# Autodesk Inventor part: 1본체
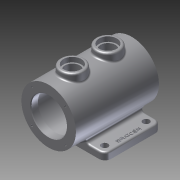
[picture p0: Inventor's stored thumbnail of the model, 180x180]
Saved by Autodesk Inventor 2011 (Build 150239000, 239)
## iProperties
Created: 2014-12
Part Number: 1본체
Document SubType Name: Modeling
Designer: user
Density: 1 g/cm^3
Mass: 477.257 g
Surface Area: 1040.04 cm^2
Volume: 477.257 cm^3
Author: user
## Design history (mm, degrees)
sketch "스케치1"
  geometry: L1 (0, 0)-(130, 0); L2 (130, 0)-(130, 95); L3 (130, 95)-(0, 95); L4 (0, 95)-(0, 0)
  constraints: 8 end point, 2 parallel, 1 horizontal, 1 perpendicular
  dimensions: "d0" = 130 distance of L3.end L2.end; "d1" = 95 distance of L2.end L1.end
extrude "돌출1" new body sketch "스케치1" distance "d2" = 12; taper "d3" = 0 deg
sketch "스케치2" dims "d23" = 37.5
  geometry: L1 (0, 0)-(0, 12) reference; L2 (0, 0)-(130, 0) reference; L3 (130, 12)-(130, 0) reference; L4 (130, 0)-(0, 0) reference; L5 (0, 0)-(0, 12) reference; L6 (0, 12)-(130, 12) reference; C1 r 46 at (65, 50)
  constraints: 1 centre point
  dimensions: "d4" = 92 diameter of C1; "d5" = 50 distance from line of L2 C1.centre; "d6" = 65 distance from line of L1 C1.centre
extrude "돌출2" join sketch "스케치2" distance "d7" = 30; taper "d9" = 0 deg; dims "d8" = 110, "d10" = 0
node "작업 평면1"
sketch "스케치3"
  geometry: L1 (-96, -30)-(-96, 110) reference; L2 (-96, 110)-(-4, 110) reference; L3 (-4, 110)-(-4, 95) reference; L4 (-4, 95)-(0, 95) reference; L5 (0, 95)-(0, 0) reference; L6 (0, 0)-(-4, 0) reference; L7 (-4, 0)-(-4, -30) reference; L8 (-4, -30)-(-96, -30) reference; L9 (-106, -10)-(-58.648, -10); L10 (-58.648, -10)-(-58.648, 10); L11 (-58.648, 10)-(-106, 10); L12 (-106, 10)-(-106, -10)
  constraints: 8 end point, 2 parallel, 1 horizontal, 1 perpendicular
  dimensions: "d11" = 40 distance between parallel lines of L8 L11; "d12" = 20 distance of L11.end L9.start; "d13" = 106 distance between parallel lines of L5 L12
revolve "회전1" sketch "스케치3" stored, may be unused: angle "d14" = 90 deg
sketch "스케치4"
  geometry: L1 (-4, 0)-(-4, -30) reference; L2 (-4, -30)-(-96, -30) reference; L3 (-96, -30)-(-96, -10) reference; L4 (-96, -10)-(-106, -10) reference; L5 (-106, -10)-(-106, 30) reference; L6 (-106, 30)-(-96, 30) reference; L7 (-96, 30)-(-96, 110) reference; L8 (-96, 110)-(-4, 110) reference; L9 (-4, 110)-(-4, 95) reference; L10 (-4, 95)-(0, 95) reference; L11 (0, 95)-(0, 0) reference; L12 (0, 0)-(-4, 0) reference; L13 (-106, 70)-(-64.183, 70); L14 (-64.183, 70)-(-64.183, 90); L15 (-64.183, 90)-(-106, 90); L16 (-106, 90)-(-106, 70)
  constraints: 8 end point, 2 parallel, 1 horizontal, 1 perpendicular
  dimensions: "d15" = 40 distance between parallel lines of L8 L13; "d16" = 20 distance of L15.end L13.start; "d17" = 106 distance between parallel lines of L11 L16
revolve "회전2" sketch "스케치4" stored, may be unused: angle "d18" = 90 deg
node "작업 평면2"
sketch "스케치5"
  geometry: L1 (-111, -30)-(-111, 110) reference; L2 (-111, 110)-(-19, 110) reference; L3 (-19, 110)-(-19, -30) reference; L4 (-19, -30)-(-111, -30) reference; L5 (-95, -42.03)-(-65, -42.03); L6 (-65, -42.03)-(-65, 144.703); L7 (-65, 144.703)-(-95, 144.703); L8 (-102.5, -18)-(-95, -18); L9 (-65, -18)-(-65, 98); L10 (-95, 98)-(-102.5, 98); L11 (-102.5, 98)-(-102.5, -18); L12 (-95, 144.703)-(-95, 98); L13 (-95, -18)-(-95, -42.03); 1 further point
  constraints: 18 end point, 5 parallel, 2 horizontal, 2 perpendicular, 1 point on line
  dimensions: "d20" = 46 distance between parallel lines of L1 L6; "d21" = 92 distance between parallel lines of L3 L1 (derived); "d23" = 37.5 distance between parallel lines of L6 L11; "d24" = 12 distance between parallel lines of L2 L10; "d25" = 12 distance between parallel lines of L4 L8
revolve "회전3" sketch "스케치5" stored, may be unused: angle "d26" = 90 deg
sketch "스케치6"
  geometry: C1 r 20 at (0, 0) reference; C2 r 20 at (0, -60) reference; 3 further points
  constraints: 2 coincident
hole "Hole1" sketch "스케치6" at (0, 0), (0, -60) diameter "d27" = 25; stored, may be unused: countersink angle "d31" = 90 deg, drill point angle "d33" = 118 deg; dims "d28" = 6, "d29" = 30, "d30" = 8, "d32" = 30
sketch "스케치7"
  geometry: L1 (0, 0)-(-53.702, 53.702); L2 (0, 0)-(75.945, 0); L3 (0, 0)-(0, 40); C1 r 46 at (0, 0) reference; C2 r 30 at (0, 0) reference; A1 r 40 centre (0, 0) between (-28.284, 28.284) and (0, 40); 1 further point
  constraints: 6 end point, 2 coincident, 2 point on circle, 1 centre point, 1 equal length, 1 horizontal, 1 point on line
  dimensions: "d34" = 135 deg angle of L2 L1; "d35" = 80 diameter of A1
hole "Hole2" sketch "스케치7" at (-28.284, 28.284) diameter "d36" = 3.242; stored, may be unused: countersink angle "d40" = 90 deg, drill point angle "d42" = 118 deg; dims "d37" = 8, "d38" = 30, "d39" = 8, "d41" = 10
node "작업 평면3"
fillet "모깎기1" dims "d46" = 10
sketch "스케치8"
  geometry: L1 (90.923, 110)-(90.923, 95) reference; L2 (90.923, 95)-(90.923, 0) reference; L3 (120, 0)-(90.923, 0) reference; L4 (130, 85)-(130, 10) reference; L5 (90.923, 95)-(120, 95) reference; L6 (39.077, 110)-(90.923, 110) reference; L7 (39.077, 95)-(39.077, 110) reference; L8 (10, 95)-(39.077, 95) reference; L9 (0, 10)-(0, 85) reference; L10 (39.077, 0)-(10, 0) reference; L11 (39.077, -30)-(39.077, 0) reference; L12 (90.923, -30)-(39.077, -30) reference; L13 (90.923, 0)-(90.923, -30) reference; L14 (39.077, 0)-(39.077, 95) reference; L15 (65, 120.179)-(65, -80.262); A1 r 10 centre (120, 10) between (120, 0) and (130, 10) reference; A2 r 10 centre (120, 85) between (130, 85) and (120, 95) reference; A3 r 10 centre (10, 85) between (10, 95) and (0, 85) reference; A4 r 10 centre (10, 10) between (0, 10) and (10, 0) reference; 5 further points
  constraints: 2 end point, 1 parallel
  dimensions: "d47" = 104 distance of point (13, 82.5) point (117, 82.5); "d48" = 25.92296 distance between parallel lines of L13 L15; "d49" = 65 distance between parallel lines of L15 L4 (derived); "d50" = 52 distance from line of L15 point (117, 82.5); "d51" = 12.5 distance from line of L5 point (117, 82.5); "d52" = 12.5 distance from line of L3 point (117, 12.5)
hole "Hole3" sketch "스케치8" at (13, 82.5), (117, 82.5), (117, 12.5), (13, 12.5) diameter "d53" = 11; stored, may be unused: countersink angle "d57" = 90 deg, drill point angle "d59" = 118 deg; dims "d54" = 8, "d55" = 30, "d56" = 8, "d58" = 30
fillet "모깎기2" dims "d60" = 3
fillet "모깎기3" dims "d61" = 3
fillet "모깎기4" dims "d62" = 5
fillet "모깎기5" dims "d63" = 3
sketch "스케치9"
  geometry: L1 (103.884, 0)-(120, 0) reference; L2 (120, 95)-(103.884, 95) reference; L3 (130, 10)-(130, 85) reference; C1 r 5.5 at (117, 12.5) reference; 2 further points
  constraints: 1 other
  dimensions: "d64" = 35 vertical distance of C1.centre point (122, 47.5); "d65" = 8 distance from line of L3 point (122, 47.5)
feature "엠보싱1" sketch "스케치9" dims "d0" = 130, "d1" = 95, "d66" = 1, "d67" = 0
chamfer "모따기1" distance "d68" = 1; stored, may be unused: second distance "d69" = 2, angle "d70" = 45 deg
node "솔리드1"
pattern_circular "원형 패턴1" dims angle "d44" = 360 deg
mirror "대칭1"
node "절단 모서리 투영1"
node "절단 모서리 투영2"
node "절단 모서리 투영3"
node "절단 모서리 투영4"
node "절단 모서리 투영5"
node "절단 모서리 투영6"
